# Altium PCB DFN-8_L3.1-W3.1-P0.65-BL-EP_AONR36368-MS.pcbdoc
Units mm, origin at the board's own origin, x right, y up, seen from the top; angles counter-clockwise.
Board outline 16.08 x 16.93 mm, 2 copper layers (Top Layer, Bottom Layer), stack 0.07 mm thick; 1 components, 0 nets, 5 pads, 0 vias.
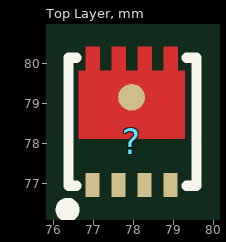
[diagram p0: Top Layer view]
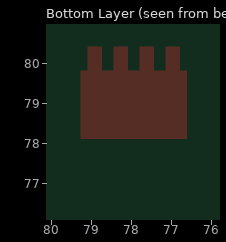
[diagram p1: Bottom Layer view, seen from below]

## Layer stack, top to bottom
Top Solder Mask Layer: solder mask 0.01, Dk 3.3
Top Layer: signal copper 0.035
Bottom Layer: signal copper 0.035
Bottom Solder Mask Layer: solder mask 0.01, Dk 3.3

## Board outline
85.925,69.85 69.85,69.85 69.85,86.78 85.925,86.78

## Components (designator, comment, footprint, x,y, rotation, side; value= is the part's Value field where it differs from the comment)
? "DFN-8_L3.1-W3.1-P0.65-BL-EP_AONR36368-MS" DFN-8_L3.1-W3.1-P0.65-BL-EP_AONR36368-MS 77.95,78.125 r0 top

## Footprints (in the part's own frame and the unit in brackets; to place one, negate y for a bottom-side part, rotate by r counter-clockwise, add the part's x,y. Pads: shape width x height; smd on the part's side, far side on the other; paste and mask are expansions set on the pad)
DFN-8_L3.1-W3.1-P0.65-BL-EP_AONR36368-MS [mm]
  rect 0.35x0.6 smd paste+0 mask+0.051: 1(-0.975,-1.155) 2(-0.325,-1.155) 3(0.325,-1.155) 4(0.975,-1.155)
  round 0.669 smd: 5(0,1.036)
  Top Layer region: 1.15,1.705 1.15,2.305 0.8,2.305 0.8,1.705 0.5,1.705 0.5,2.305 0.15,2.305 0.15,1.705 -0.15,1.705 -0.15,2.305 -0.5,2.305 -0.5,1.705 -0.8,1.705 -0.8,2.305 -1.15,2.305 -1.15,1.705 -1.325,1.705 -1.325,0.005 1.325,0.005 1.325,1.705
  silkscreen extent -1.75,-1.92 1.62,2.02

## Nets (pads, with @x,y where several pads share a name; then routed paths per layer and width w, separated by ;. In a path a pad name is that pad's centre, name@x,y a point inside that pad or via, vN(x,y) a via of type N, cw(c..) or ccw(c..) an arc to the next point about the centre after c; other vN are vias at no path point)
pads on no net: ?.1 ?.2 ?.3 ?.4 ?.5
